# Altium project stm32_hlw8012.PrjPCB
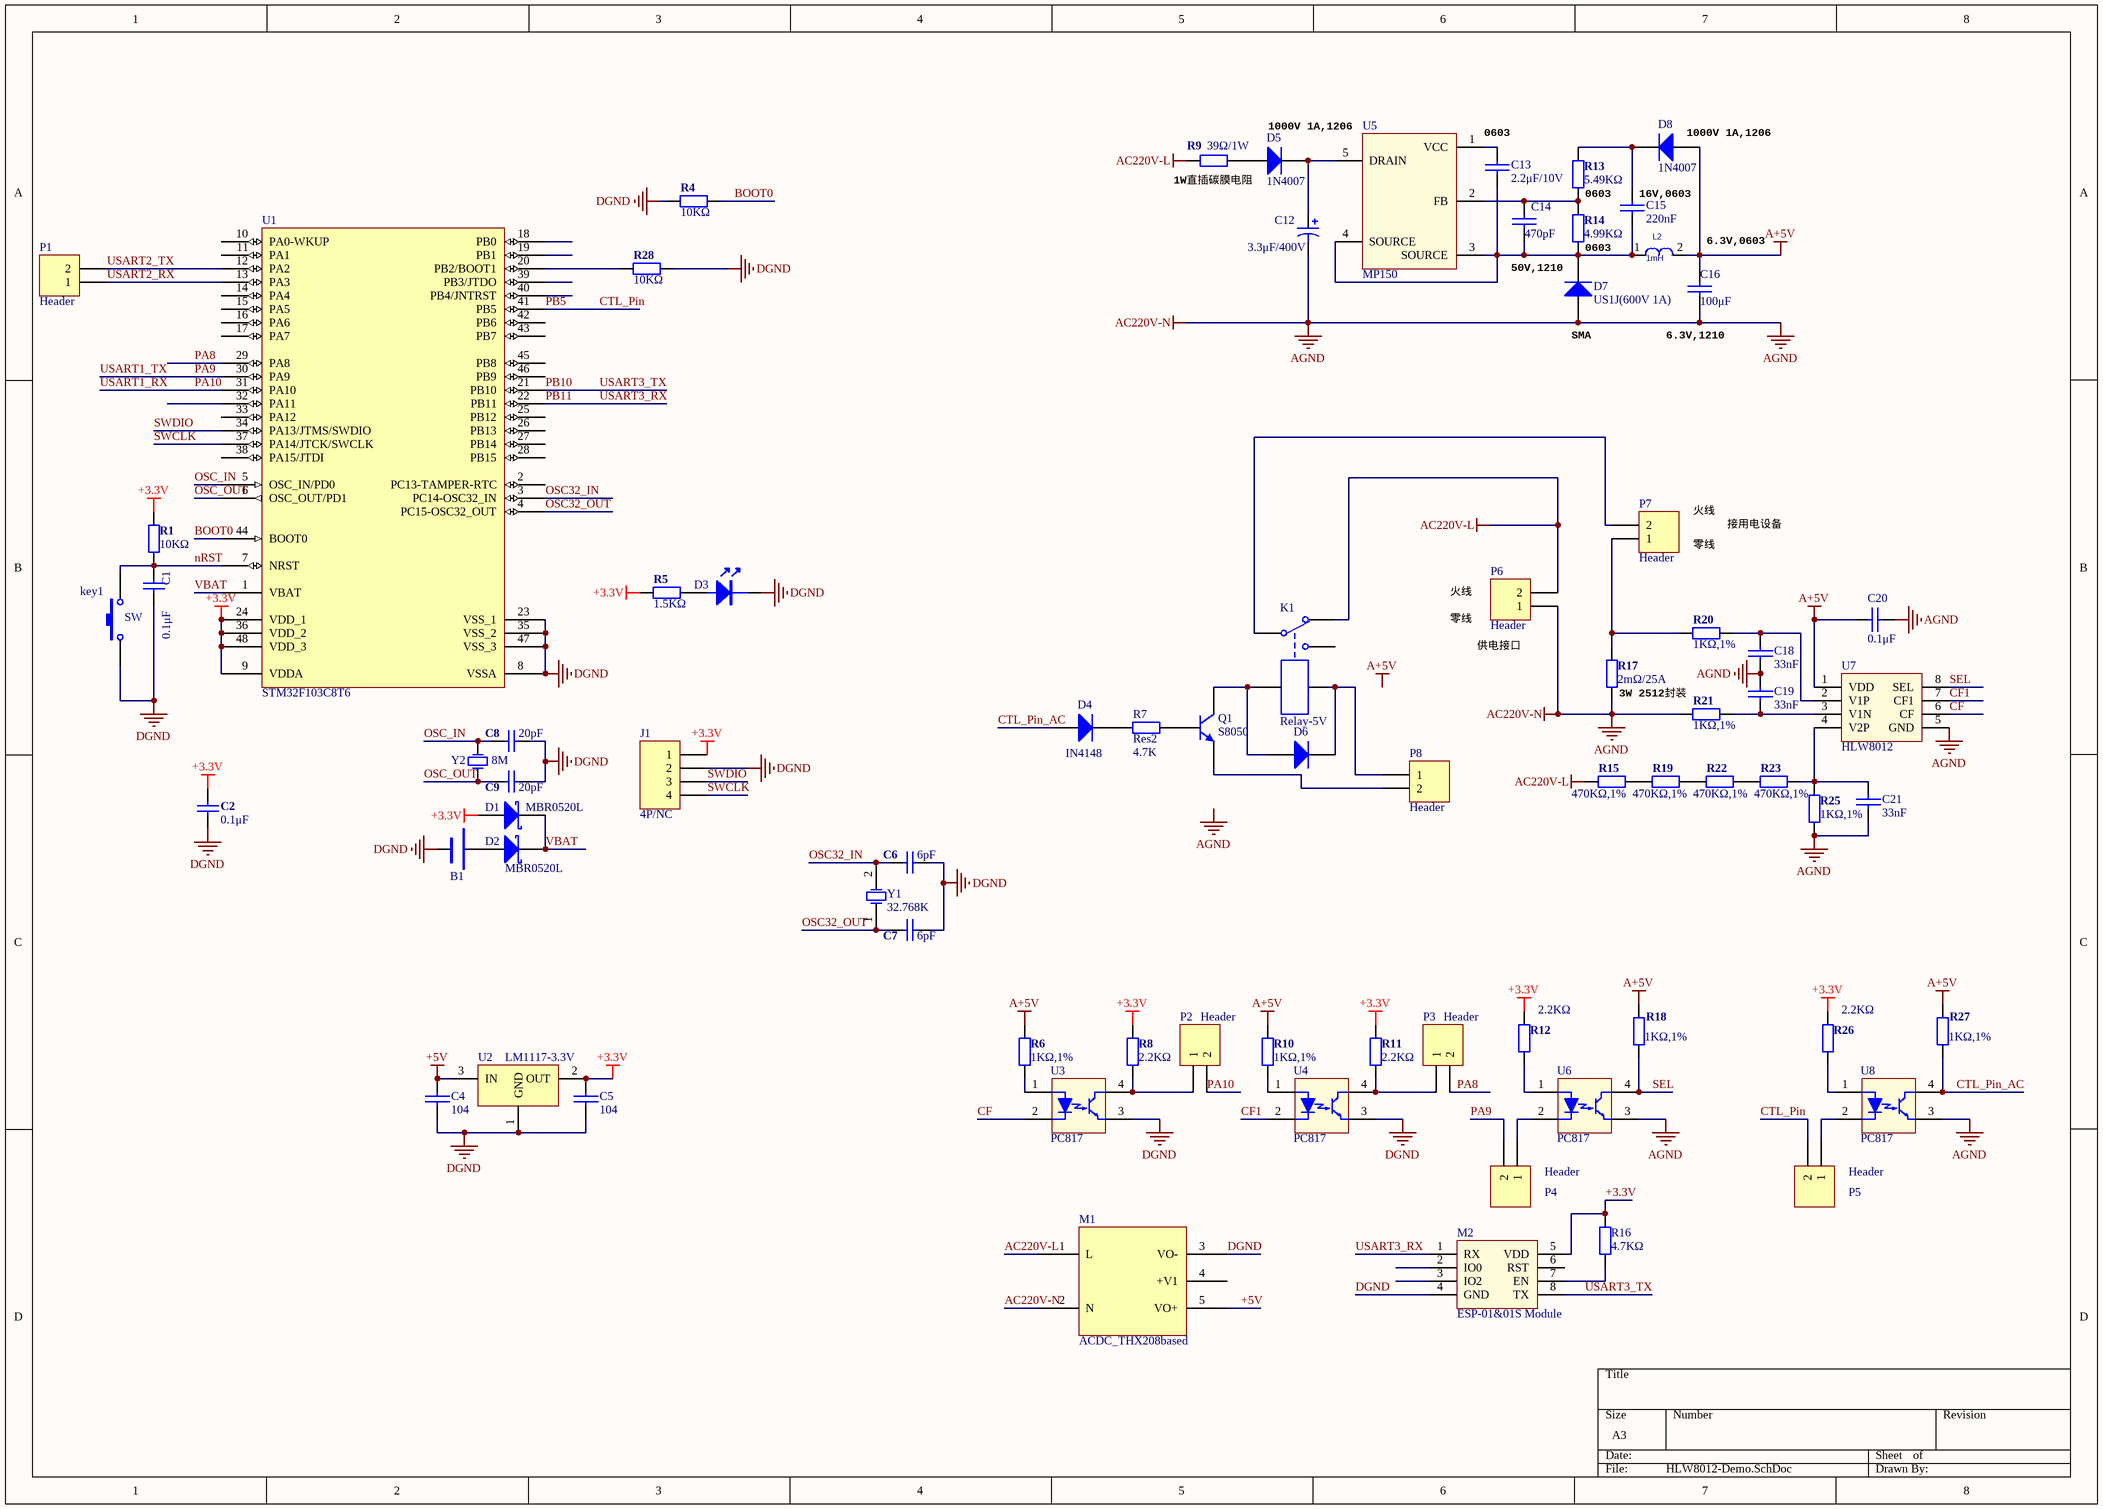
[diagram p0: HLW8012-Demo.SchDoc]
1 sheet, 76 parts. Net scope: global (net labels, ports and power ports of the same name join across sheets).
Board file: HLW8012-Demo.PcbDoc

## Sheet HLW8012-Demo.SchDoc: Smartplug
size A3

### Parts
B1  BAT  [BATTERY SOCKET]  (value not drawn)
C1  0.1μF  [LC-0603_C]
C2  0.1μF  [LC-0603_C]
C4  104  [0603C]
C5  104  [0603C]
C6  6pF  [LC-0603_C]
C7  6pF  [LC-0603_C]
C8  20pF  [LC-0603_C]
C9  20pF  [LC-0603_C]
C12  3.3μF/400V  [CAP-ELECT-TH-6.3X7]
C13  2.2μF/10V  [LC-0603_C]
C14  470pF  [LC-0603_C]
C15  220nF  [LC-0603_C]
C16  100μF  [LC-1210_C]
C18  33nF  [LC-0805_C]
C19  33nF  [LC-0805_C]
C20  0.1μF  [LC-0603_C]
C21  33nF  [LC-0805_C]
D1  MBR0520L  [LC-SOD-123]
D2  MBR0520L  [LC-SOD-123]
D3  POWER  [LC-0603_LED_S1]  (value not drawn)
D4  IN4148  [1206D]
D5  1N4007  [LC-SMA(DO-214AC)_S1]
D6  (no value)  [1206D]
D7  US1J(600V 1A)  [LC-SMA(DO-214AC)_S1]
D8  1N4007  [LC-SMA(DO-214AC)_S1]
J1  4P/NC  [HDR1X4]
K1  Relay-5V  [RLAYSPDT]
key1  SW  [KEY-2]
L2  1mH  [L-10X14]
M1  ACDC_THX208based  [ACDC_THX208]
M2  ESP-01&01S Module  [ESP-01&01S Module]
P1  Header  [HDR1X2]
P2  Header  [HDR1X2]
P3  Header  [HDR1X2]
P4  Header  [HDR1X2]
P5  Header  [HDR1X2]
P6  Header  [3.81-2P]
P7  Header  [3.81-2P]
P8  Header  [HDR1X2]
Q1  S8050  [SOT-23]
R1  10KΩ  [LC-0603_R]
R4  10KΩ  [LC-0603_R]
R5  1.5KΩ  [LC-0603_R]
R6  1KΩ,1%  [LC-0805_R]
R7  Res2  value 4.7K  [0603]
R8  2.2KΩ  [LC-0603_R]
R9  39Ω/1W  [R-1W-THT]
R10  1KΩ,1%  [LC-0805_R]
R11  2.2KΩ  [LC-0603_R]
R12  2.2KΩ  [LC-0603_R]
R13  5.49KΩ  [LC-0603_R]
R14  4.99KΩ  [LC-0603_R]
R15  470KΩ,1%  [LC-0805_R]
R16  4.7KΩ  [LC-0603_R]
R17  2mΩ/25A  [R2512]
R18  1KΩ,1%  [LC-0805_R]
R19  470KΩ,1%  [LC-0805_R]
R20  1KΩ,1%  [LC-0805_R]
R21  1KΩ,1%  [LC-0805_R]
R22  470KΩ,1%  [LC-0805_R]
R23  470KΩ,1%  [LC-0805_R]
R25  1KΩ,1%  [LC-0805_R]
R26  2.2KΩ  [LC-0603_R]
R27  1KΩ,1%  [LC-0805_R]
R28  10KΩ  [LC-0603_R]
U1  STM32F103C8T6  [LC-LQFP-48_7x7x05P]
U2  LM1117-3.3V  [SOT-223/P2.3]
U3  PC817  [LC-SMD-4]
U4  PC817  [LC-SMD-4]
U5  MP150  [LC-SOT-23-5]
U6  PC817  [LC-SMD-4]
U7  HLW8012  [LC-SOP-8_150mil]
U8  PC817  [LC-SMD-4]
Y1  32.768K  [CRYSTAL]
Y2  8M  [49/U_N]

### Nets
+3.3V: C2.2 C5.1 D1.1(A) J1.1 M2.5(VDD) R1.2 R5.2 R8.2 R11.2 R12.2 R16.2 R26.2 U1.9(VDDA) U1.24(VDD_1) U1.36(VDD_2) U1.48(VDD_3) U2.2(OUT)
+5V: C4.1 M1.5(VO+) U2.3(IN)
A+5V: C16.2 C20.1 D8.1(A) L2.2 R6.2 R10.2 R18.2 R27.2 U7.1(VDD)
AC220V-L: K1.2 M1.1(L) P6.2 R9.1 R15.2
AC220V-N: C12.2 C16.1 C18.2 C19.1 C20.2 C21.2 D7.1(A) M1.2(N) P6.1 R17.2 R21.2 R25.2 U6.3(A2) U7.5(GND) U8.3(A2)  [also labelled AGND]
DGND: B1.2 C1.1 C2.1 C4.2 C5.2 C6.2 C7.2 C8.2 C9.2 D3.K J1.2 key1.1 M1.3(VO-) M2.4(GND) R4.2 R28.1 U1.8(VSSA) U1.23(VSS_1) U1.35(VSS_2) U1.47(VSS_3) U2.1(GND) U3.3(A2) U4.3(A2)
BOOT0: R4.1 U1.44(BOOT0)
CF: U3.2(K1) U7.6(CF)
CF1: U4.2(K1) U7.7(CF1)
CTL_Pin: P5.2 U1.41(PB5)  [also labelled PB5]
CTL_Pin_AC: D4.1(A) R27.1 U8.4(K2)
nRST: C1.2 key1.2 R1.1 U1.7(NRST)
OSC32_IN: C6.1 U1.3(PC14-OSC32_IN) Y1.2(OSC2)
OSC32_OUT: C7.1 U1.4(PC15-OSC32_OUT) Y1.1(OSC1)
OSC_IN: C8.1 U1.5(OSC_IN/PD0) Y2.1
OSC_OUT: C9.1 U1.6(OSC_OUT/PD1) Y2.2
PA8: P3.2 U1.29(PA8)
PA9: P4.2 U1.30(PA9)  [also labelled USART1_TX]
PA10: P2.2 U1.31(PA10)  [also labelled USART1_RX]
PB10: M2.8(TX) U1.21(PB10)  [also labelled USART3_TX]
PB11: M2.1(RX) U1.22(PB11)  [also labelled USART3_RX]
SEL: R18.1 U6.4(K2) U7.8(SEL)
SWCLK: J1.4 U1.37(PA14/JTCK/SWCLK)
SWDIO: J1.3 U1.34(PA13/JTMS/SWDIO)
USART2_RX: P1.1 U1.13(PA3)
USART2_TX: P1.2 U1.12(PA2)
VBAT: D1.2(K) D2.2(K) U1.1(VBAT)
NetB1_1: B1.1 D2.1(A)
NetC12_1: C12.1 D5.2(K) U5.5(DRAIN)
NetC13_1: C13.1 C14.1 C15.1 D7.2(K) L2.1 R14.1 U5.3(SOURCE) U5.4(SOURCE)
NetC13_2: C13.2 U5.1(VCC)
NetC14_2: C14.2 R13.1 R14.2 U5.2(FB)
NetC15_2: C15.2 D8.2(K) R13.2
NetC18_1: C18.1 R20.1 U7.2(V1P)
NetC19_2: C19.2 R21.1 U7.3(V1N)
NetC21_1: C21.1 R23.1 R25.1 U7.4(V2P)
NetD3_A: D3.A R5.1
NetD4_2: D4.2(K) R7.2
NetD5_1: D5.1(A) R9.2
NetD6_1: D6.1(A) K1.4 Q1.3(C)
NetD6_2: D6.2(K) K1.5 P8.1
NetK1_1: K1.1 P7.2
NetM2_7: M2.7(EN) R16.1
NetP2_1: P2.1 R8.1 U3.4(K2)
NetP3_1: P3.1 R11.1 U4.4(K2)
NetP4_1: P4.1 U6.2(K1)
NetP5_1: P5.1 U8.2(K1)
NetP7_1: P7.1 R17.1 R20.2
NetP8_2: P8.2 Q1.2(E)
NetQ1_1: Q1.1(B) R7.1
NetR6_1: R6.1 U3.1(A1)
NetR10_1: R10.1 U4.1(A1)
NetR12_1: R12.1 U6.1(A1)
NetR15_1: R15.1 R19.2
NetR19_1: R19.1 R22.2
NetR22_1: R22.1 R23.2
NetR26_1: R26.1 U8.1(A1)
NetR28_2: R28.2 U1.20(PB2/BOOT1)

Not connected (* = marked no-connect by the designer): K1 3; M1 4(+V1); M2 2(IO0) 3(IO2) 6(RST); U1 2(PC13-TAMPER-RTC) 10(PA0-WKUP) 11(PA1) 14(PA4) 15(PA5) 16(PA6) 17(PA7) 18(PB0) 19(PB1) 25(PB12) 26(PB13) 27(PB14) 28(PB15) 32(PA11) 33(PA12) 38(PA15/JTDI) 39(PB3/JTDO) 40(PB4/JNTRST) 42(PB6) 43(PB7) 45(PB8) 46(PB9)

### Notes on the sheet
- (near R9) 1W直插碳膜电阻
- 1000V 1A,1206
- 0603
- (near D8) 1000V 1A,1206
- (near R13) 0603
- (near C15) 16V,0603
- 6.3V,0603
- 50V,1210
- (near R14) 0603
- (near D7) SMA
- (near C16) 6.3V,1210
- 火线
- 零线
- 接用电设备
- (near P6) 供电接口
- (near R17) 3W 2512封装
- Labels drawn without touching a wire or pin: A+5V, AGND

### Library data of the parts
B1 = BAT: 电池; Value: 红色
C1 C2 C6-C9 = Cap: 贴片电容; 名称: 电容; 封装: 0805; 型号: 1μF
C4 C5 = CAP: Capacitor
C12 = Cap Pol1: 直插电解电容; Value: 2.2μF/400V
C13-C16 C18-C21 = CAP: 贴片电容; Value: 100nF (104) ±10% 50V
D1 D2 = Diode 18TQ045: 贴片肖特基二极管; Note: Terminal 2 is the TAB and is electrically connected to the cathode
D3 = LED1: 发光二极管; Value: 红色
D4 D6 = Diode: Default Diode
D5 D7 D8 = Diode 1N5408: 贴片二极管
J1 = Header 4: 接口
K1 = Relay-SPDT: Single-Pole Dual-Throw Relay
key1 = SW: Switch
L2 = IND_8: 直插绕线电感; CISPartType: Inductor\Ferrite; OriginalSymbolOrigin: (0,0); ATHEROS KEY: 078-100LM-000; AtherosDescription: IND,SMT,SHIELDING CHOKE,10uH,7.3x7.3
M1 = ACDC: THX208Based
P1-P8 = Header 2: Header, 2-Pin
Q1 = NPN: NPN Bipolar Transistor
R1 R4 R5 R8 R9 R11-R15 R17 R19 R22 R23 R26 R28 = 电阻: 贴片电阻; 型号: 1KΩ
R6 R10 R18 R20 R21 R25 R27 = 电阻: 贴片电阻
R7 = Res2: Resistor
R16 = 0805 62KΩ (6202) 1%: 贴片电阻
U1 = STM32F103CBT6: IC; 封装: LQFP48; 厂商: ST
U2 = 1117
U3 U4 U6 U8 = PS2501L-1-F3-A: IC
U5 = MP150: IC
U7 = HLW8012: IC
Y1 = XTAL: Crystal Oscillator
Y2 = XTAL_1: 晶振（直插）; Value: 25MHz ±20ppm 20pF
